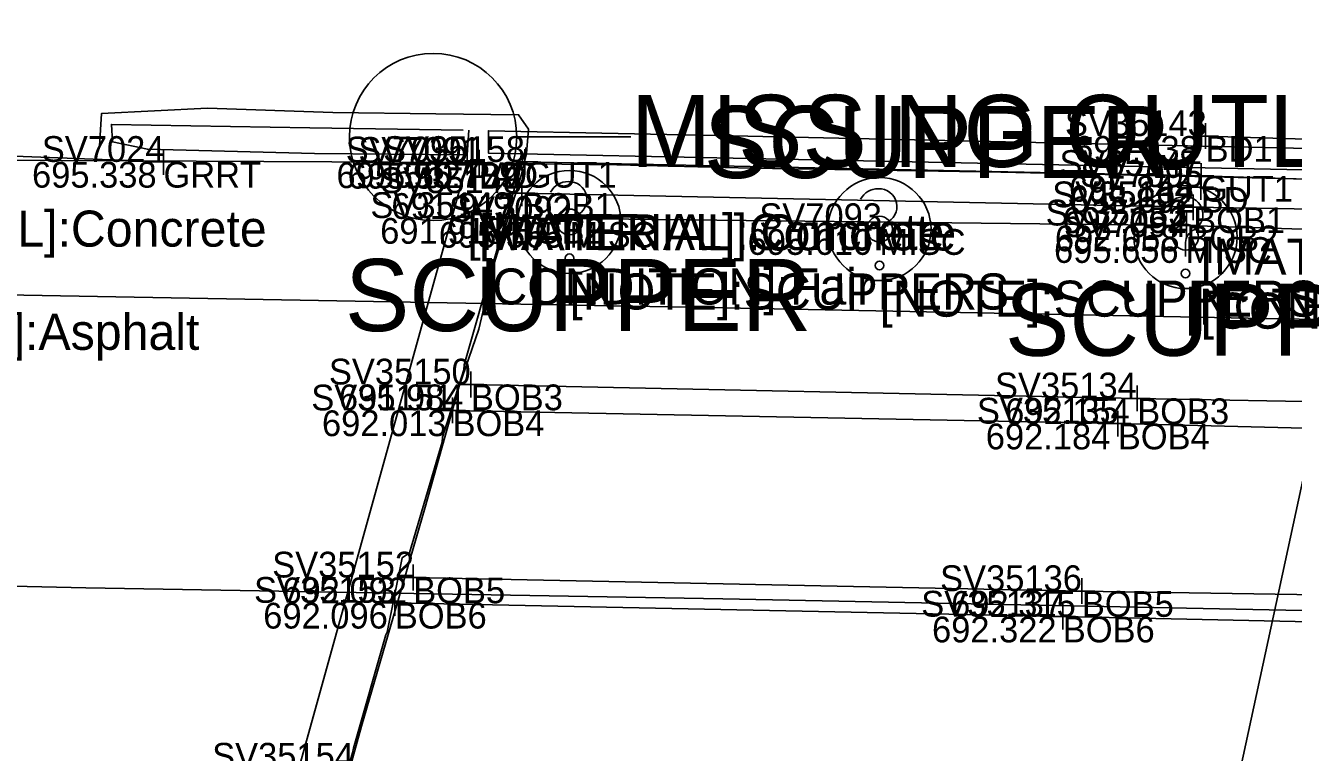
# Model space of a CAD drawing. Extents: x 1659932 to 1663108, y 619867 to 620611.
# Drawn here: x 1661219.34 to 1661268.55, y 620227.86 to 620256.09 of the extents above; entities that cross this region are included whole.
import ezdxf

# ---------------------------------------------------------------- set-up
doc = ezdxf.new("R2010")
doc.units = 0
for name, color, linetype in [('BR_X_Rail_Object', 7, 'Continuous'), ('BR_X_SV_Abut', 7, 'Continuous'), ('BR_X_SV_Bottom_of_Beam', 7, 'Continuous'), ('BR_X_SV_Bottom_of_Beam_Text', 7, 'Continuous'), ('BR_X_SV_Deck_Top', 7, 'Continuous'), ('BR_X_SV_Deck_Top_Text', 7, 'Continuous'), ('PM_X_CL_Double_Solid', 7, 'Continuous'), ('PM_X_Edge_Line', 7, 'Continuous'), ('PV_X_Curb', 7, 'Continuous'), ('RD_X_Concrete_Pad', 7, 'Continuous'), ('RD_X_GR_Rt', 7, 'Continuous'), ('RD_X_Misc_Items', 7, 'Continuous'), ('RD_X_Text', 7, 'Continuous'), ('SC_Scratch6', 7, 'Continuous'), ('SV_X_Break_Lines', 7, 'Continuous'), ('SV_X_Shot_Marker', 7, 'Continuous'), ('SV_X_Text', 7, 'Continuous'), ('SV_X_Text_Comment', 7, 'Continuous'), ('SV_X_Text_Elevation', 7, 'Continuous'), ('SV_X_Text_Name', 7, 'Continuous'), ('SV_X_Toe_of_Slope', 7, 'Continuous')]:
    doc.layers.add(name, color=color, linetype=linetype)

msp = doc.modelspace()

# ---------------------------------------------------------------- linework, layer by layer
at = {"layer": 'BR_X_Rail_Object'}
for points in [[(1661236.541, 620252.029), (1661236.482, 620251.069), (1661230.55, 620251.115), (1661224.071, 620251.281), (1661222.711, 620251.568), (1661222.675, 620252.248), (1661230.372, 620252.112), (1661236.319, 620252.019)], [(1661312.412, 620250.402), (1661292.245, 620250.78), (1661270.899, 620251.272), (1661247.366, 620251.791), (1661237.299, 620252), (1661237.309, 620251.128), (1661247.431, 620250.924), (1661270.809, 620250.444), (1661292.272, 620249.911), (1661312.353, 620249.471)]]:
    msp.add_lwpolyline(points, dxfattribs=at)
at = {"layer": 'BR_X_SV_Abut'}
msp.add_lwpolyline([(1661228.902, 620216.979), (1661231.137, 620224.905), (1661231.223, 620225.092), (1661232.028, 620227.843), (1661232.073, 620228.025), (1661233.318, 620232.429), (1661233.369, 620232.535), (1661233.962, 620235.423), (1661234.24, 620235.614), (1661235.509, 620239.905), (1661235.523, 620240.11), (1661236.345, 620242.714), (1661236.356, 620242.915), (1661238.766, 620251.347)], dxfattribs=at)
at = {"layer": 'BR_X_SV_Bottom_of_Beam'}
for points in [[(1661523.404, 620243.849), (1661497.415, 620244.383), (1661471.694, 620244.95), (1661445.773, 620245.45), (1661419.903, 620245.974), (1661394.009, 620246.51), (1661368.147, 620247.032), (1661342.287, 620247.488), (1661316.311, 620248.045), (1661290.557, 620248.602), (1661264.648, 620249.031), (1661238.6, 620249.579)], [(1661517.582, 620243.008), (1661496.897, 620243.44), (1661470.919, 620243.838), (1661445.09, 620244.441), (1661419.147, 620244.946), (1661393.26, 620245.417), (1661367.358, 620245.921), (1661341.629, 620246.518), (1661315.646, 620247.115), (1661289.746, 620247.518), (1661264.383, 620248.322), (1661238.204, 620248.614)], [(1661521.265, 620236.365), (1661495.332, 620236.959), (1661469.491, 620237.512), (1661443.572, 620237.996), (1661417.708, 620238.508), (1661391.884, 620239.08), (1661365.994, 620239.561), (1661340.119, 620240.034), (1661314.197, 620240.589), (1661288.354, 620241.145), (1661262.476, 620241.611), (1661236.623, 620242.15)], [(1661520.605, 620235.452), (1661494.63, 620235.975), (1661468.71, 620236.383), (1661442.944, 620236.996), (1661417.103, 620237.514), (1661391.103, 620237.982), (1661365.202, 620238.448), (1661339.374, 620239.07), (1661313.502, 620239.591), (1661287.59, 620239.99), (1661261.723, 620240.632), (1661235.908, 620241.144)], [(1661519.081, 620228.953), (1661493.234, 620229.438), (1661467.368, 620230.031), (1661441.422, 620230.57), (1661415.6, 620231.071), (1661389.731, 620231.651), (1661363.823, 620232.132), (1661337.817, 620232.613), (1661311.988, 620233.076), (1661286.183, 620233.721), (1661260.328, 620234.129), (1661234.382, 620234.656)], [(1661518.51, 620227.977), (1661492.527, 620228.475), (1661466.56, 620228.954), (1661440.742, 620229.56), (1661414.823, 620230.069), (1661388.938, 620230.522), (1661363.07, 620231.021), (1661337.298, 620231.612), (1661311.527, 620232.162), (1661285.446, 620232.587), (1661259.588, 620233.138), (1661233.669, 620233.674)]]:
    msp.add_lwpolyline(points, dxfattribs=at)
at = {"layer": 'BR_X_SV_Deck_Top'}
msp.add_lwpolyline([(1661524.154, 620246.519), (1661498.291, 620247.067), (1661472.426, 620247.598), (1661446.524, 620248.074), (1661420.55, 620248.604), (1661394.772, 620249.021), (1661368.927, 620249.743), (1661342.743, 620250.117), (1661316.866, 620250.706), (1661291.246, 620251.013), (1661265.132, 620251.796)], dxfattribs=at)
at = {"layer": 'PM_X_CL_Double_Solid'}
msp.add_lwpolyline([(1661546.991, 620228.003), (1661534.02, 620228.314), (1661515.703, 620228.672), (1661490.63, 620229.199), (1661465.719, 620229.574), (1661443.889, 620229.917), (1661424.27, 620230.219), (1661405.796, 620230.53), (1661384.669, 620230.881), (1661362.569, 620231.272), (1661341.508, 620231.739), (1661317.992, 620232.235), (1661293.686, 620232.891), (1661270.168, 620233.351), (1661246.396, 620233.829), (1661221.676, 620234.257), (1661205.714, 620234.618)], dxfattribs=at)
at = {"layer": 'PM_X_Edge_Line'}
msp.add_lwpolyline([(1661550.118, 620239.201), (1661538.667, 620239.519), (1661512.091, 620240.179), (1661488.878, 620240.663), (1661465.84, 620241.071), (1661441.891, 620241.445), (1661414.819, 620241.887), (1661388.375, 620242.338), (1661361.281, 620242.854), (1661333.713, 620243.371), (1661302.167, 620244.004), (1661273.353, 620244.591), (1661246.421, 620245.132), (1661216.402, 620245.664), (1661208.501, 620245.807)], dxfattribs=at)
at = {"layer": 'PV_X_Curb'}
msp.add_lwpolyline([(1661523.342, 620245.121), (1661471.566, 620246.113), (1661445.996, 620246.597), (1661316.22, 620249.01), (1661290.79, 620249.439), (1661264.952, 620250.247), (1661238.714, 620250.79)], dxfattribs=at)
at = {"layer": 'RD_X_Concrete_Pad'}
msp.add_lwpolyline([(1661227.337, 620217.837), (1661200.851, 620218.632), (1661210.18, 620250.901), (1661236.479, 620250.773)], close=True, dxfattribs=at)
at = {"layer": 'RD_X_GR_Rt'}
msp.add_lwpolyline([(1661224.694, 620250.792), (1661156.18, 620253.354), (1661087.544, 620257.195), (1661037.259, 620258.502), (1660981.367, 620259.471), (1660918.677, 620260.81), (1660856.774, 620262.085), (1660800.696, 620262.738), (1660750.309, 620264.537), (1660700.275, 620265.164), (1660644.426, 620266.521), (1660592.862, 620267.531)], dxfattribs=at)
at = {"layer": 'RD_X_Misc_Items'}
for p, q in [((1661240.447, 620247.706), (1661240.447, 620248.181)), ((1661252.475, 620247.427), (1661252.475, 620247.902)), ((1661264.352, 620247.116), (1661264.352, 620247.591))]:
    msp.add_line(p, q, dxfattribs=at)
for centre, radius in [((1661240.447, 620248.461), 2), ((1661252.475, 620248.182), 2), ((1661264.352, 620247.871), 2), ((1661240.447, 620248.461), 0.5), ((1661240.447, 620248.461), 0.5), ((1661252.475, 620248.182), 0.5), ((1661252.475, 620248.182), 0.5), ((1661264.352, 620247.871), 0.5), ((1661264.352, 620247.871), 0.5), ((1661240.447, 620247.049), 0.17), ((1661252.475, 620246.77), 0.17), ((1661264.352, 620246.459), 0.17)]:
    msp.add_circle(centre, radius, dxfattribs=at)
for centre, radius, start, end in [((1661240.383, 620249.272), 0.754, 88.324, 152.5385), ((1661240.435, 620249.339), 0.688, 291.9329, 92.4584), ((1661252.411, 620248.993), 0.754, 88.324, 152.5385), ((1661252.463, 620249.06), 0.688, 291.9329, 92.4584), ((1661264.288, 620248.682), 0.754, 88.324, 152.5385), ((1661264.34, 620248.749), 0.688, 291.9329, 92.4584), ((1661241.033, 620248.223), 0.587, 125.4618, 184.0829), ((1661253.061, 620247.944), 0.587, 125.4618, 184.0829), ((1661264.938, 620247.633), 0.587, 125.4618, 184.0829)]:
    msp.add_arc(centre, radius, start, end, dxfattribs=at)
at = {"layer": 'SC_Scratch6'}
msp.add_line((1661238.401, 620251.76), (1661242.831, 620251.76), dxfattribs=at)
msp.add_circle((1661235.157, 620251.76), 3.245, dxfattribs=at)
at = {"layer": 'SV_X_Break_Lines'}
for points in [[(1661238.852, 620252.06), (1661238.474, 620252.623), (1661235.256, 620252.659), (1661231.268, 620252.711), (1661226.404, 620252.881), (1661222.29, 620252.676), (1661222.214, 620251.401)], [(1661228.886, 620216.719), (1661229.498, 620218.302), (1661229.927, 620220.312), (1661230.763, 620223.207), (1661231.636, 620226.217), (1661232.38, 620228.883), (1661234.027, 620234.579), (1661234.843, 620237.386), (1661236.169, 620242.084), (1661236.935, 620244.302), (1661237.536, 620246.886), (1661238.567, 620250.261), (1661238.784, 620251.123), (1661238.852, 620252.06)], [(1661238.016, 620250.735), (1661242.286, 620250.672), (1661247.517, 620250.551), (1661257.182, 620250.394), (1661265.859, 620250.202), (1661279.254, 620249.879), (1661300.715, 620249.466), (1661326.88, 620248.933), (1661355.543, 620248.374), (1661388.796, 620247.704), (1661434.33, 620246.78), (1661467.071, 620246.096), (1661484, 620245.717), (1661498.395, 620245.527), (1661509.52, 620245.356), (1661518.819, 620245.069), (1661524.432, 620245.01)]]:
    msp.add_lwpolyline(points, dxfattribs=at)
at = {"layer": 'SV_X_Shot_Marker'}
for p, q in [((1661265.132, 620252.296), (1661265.132, 620251.296)), ((1661264.632, 620251.796), (1661265.632, 620251.796)), ((1661265.132, 620251.796), (1661265.132, 620251.796)), ((1661224.694, 620251.292), (1661224.694, 620250.292)), ((1661236.479, 620251.273), (1661236.479, 620250.273)), ((1661236.937, 620251.254), (1661236.937, 620250.254)), ((1661238.714, 620251.29), (1661238.714, 620250.29)), ((1661224.194, 620250.792), (1661225.194, 620250.792)), ((1661224.694, 620250.792), (1661224.694, 620250.792)), ((1661235.979, 620250.773), (1661236.979, 620250.773)), ((1661236.437, 620250.754), (1661237.437, 620250.754)), ((1661236.479, 620250.773), (1661236.479, 620250.773)), ((1661236.937, 620250.754), (1661236.937, 620250.754)), ((1661238.214, 620250.79), (1661239.214, 620250.79)), ((1661238.714, 620250.79), (1661238.714, 620250.79)), ((1661264.952, 620250.747), (1661264.952, 620249.747)), ((1661238.6, 620250.079), (1661238.6, 620249.079)), ((1661264.452, 620250.247), (1661265.452, 620250.247)), ((1661264.939, 620250.315), (1661264.939, 620249.315)), ((1661264.952, 620250.247), (1661264.952, 620250.247)), ((1661238.1, 620249.579), (1661239.1, 620249.579)), ((1661238.6, 620249.579), (1661238.6, 620249.579)), ((1661264.439, 620249.815), (1661265.439, 620249.815)), ((1661264.648, 620249.531), (1661264.648, 620248.531)), ((1661264.939, 620249.815), (1661264.939, 620249.815)), ((1661238.204, 620249.114), (1661238.204, 620248.114)), ((1661264.148, 620249.031), (1661265.148, 620249.031)), ((1661264.648, 620249.031), (1661264.648, 620249.031)), ((1661237.704, 620248.614), (1661238.704, 620248.614)), ((1661238.204, 620248.614), (1661238.204, 620248.614)), ((1661264.383, 620248.822), (1661264.383, 620247.822)), ((1661263.883, 620248.322), (1661264.883, 620248.322)), ((1661264.383, 620248.322), (1661264.383, 620248.322)), ((1661236.623, 620242.65), (1661236.623, 620241.65)), ((1661236.123, 620242.15), (1661237.123, 620242.15)), ((1661236.623, 620242.15), (1661236.623, 620242.15)), ((1661262.476, 620242.111), (1661262.476, 620241.111)), ((1661235.908, 620241.644), (1661235.908, 620240.644)), ((1661261.976, 620241.611), (1661262.976, 620241.611)), ((1661262.476, 620241.611), (1661262.476, 620241.611)), ((1661235.408, 620241.144), (1661236.408, 620241.144)), ((1661235.908, 620241.144), (1661235.908, 620241.144)), ((1661261.723, 620241.132), (1661261.723, 620240.132)), ((1661261.223, 620240.632), (1661262.223, 620240.632)), ((1661261.723, 620240.632), (1661261.723, 620240.632)), ((1661234.382, 620235.156), (1661234.382, 620234.156)), ((1661233.882, 620234.656), (1661234.882, 620234.656)), ((1661234.382, 620234.656), (1661234.382, 620234.656)), ((1661260.328, 620234.629), (1661260.328, 620233.629)), ((1661233.669, 620234.174), (1661233.669, 620233.174)), ((1661259.828, 620234.129), (1661260.828, 620234.129)), ((1661260.328, 620234.129), (1661260.328, 620234.129)), ((1661233.169, 620233.674), (1661234.169, 620233.674)), ((1661233.669, 620233.674), (1661233.669, 620233.674)), ((1661259.588, 620233.638), (1661259.588, 620232.638)), ((1661259.088, 620233.138), (1661260.088, 620233.138)), ((1661259.588, 620233.138), (1661259.588, 620233.138))]:
    msp.add_line(p, q, dxfattribs=at)
at = {"layer": 'SV_X_Toe_of_Slope'}
msp.add_lwpolyline([(1661237.229, 620169.637), (1661259.655, 620195.623), (1661277.405, 620277.795), (1661264.309, 620300.267)], dxfattribs=at)

# ---------------------------------------------------------------- texts
at = {"layer": 'BR_X_SV_Bottom_of_Beam_Text'}
for s, p in [('SV35148', (1661233.103, 620249.579)), ('SV35132', (1661259.179, 620249.031)), ('SV35149', (1661232.724, 620248.614)), ('691.913', (1661233.536, 620248.579)), ('BOB1', (1661238.6, 620248.579)), ('SV35133', (1661258.923, 620248.322)), ('692.052', (1661259.575, 620248.031)), ('BOB1', (1661264.648, 620248.031)), ('691.918', (1661233.104, 620247.614)), ('BOB2', (1661238.204, 620247.614)), ('692.058', (1661259.283, 620247.322)), ('BOB2', (1661264.383, 620247.322)), ('SV35150', (1661231.113, 620242.15)), ('SV35134', (1661256.958, 620241.611)), ('SV35151', (1661230.43, 620241.144)), ('691.984', (1661231.501, 620241.15)), ('BOB3', (1661236.623, 620241.15)), ('SV35135', (1661256.256, 620240.632)), ('692.154', (1661257.354, 620240.611)), ('BOB3', (1661262.476, 620240.611)), ('692.013', (1661230.844, 620240.144)), ('BOB4', (1661235.908, 620240.144)), ('692.184', (1661256.601, 620239.632)), ('BOB4', (1661261.723, 620239.632)), ('SV35152', (1661228.913, 620234.656)), ('SV35136', (1661254.828, 620234.129)), ('SV35153', (1661228.209, 620233.674)), ('692.092', (1661229.309, 620233.656)), ('BOB5', (1661234.382, 620233.656)), ('SV35137', (1661254.096, 620233.138)), ('692.315', (1661255.258, 620233.129)), ('BOB5', (1661260.328, 620233.129)), ('692.096', (1661228.565, 620232.674)), ('BOB6', (1661233.669, 620232.674)), ('692.322', (1661254.515, 620232.138)), ('BOB6', (1661259.588, 620232.138)), ('SV35154', (1661226.582, 620227.235))]:
    msp.add_text(s, height=1, dxfattribs=at).set_placement(p)
at = {"layer": 'BR_X_SV_Deck_Top_Text'}
for s, p in [('SV35143', (1661259.672, 620251.796)), ('SV7091', (1661232.257, 620250.754)), ('695.038', (1661260.032, 620250.796)), ('BD1', (1661265.132, 620250.796)), ('695.507', (1661231.841, 620249.754)), ('BD', (1661236.937, 620249.754)), ('SV7095', (1661260.27, 620249.815)), ('695.692', (1661259.866, 620248.815)), ('BD', (1661264.939, 620248.815))]:
    msp.add_text(s, height=1, dxfattribs=at).set_placement(p)
at = {"layer": 'RD_X_Text'}
for p in [(1661245.663, 620250.164), (1661231.736, 620244.222), (1661257.344, 620243.265)]:
    msp.add_text('SCUPPER', height=2.8, dxfattribs=at).set_placement(p)
at = {"layer": 'SC_Scratch6'}
msp.add_text('MISSING OUTLINE OF ABUTMENT', height=2.79999, dxfattribs=at).set_placement((1661242.831, 620250.594))
at = {"layer": 'SV_X_Text'}
for s, p in [('[MATERIAL]:Concrete', (1661210.18, 620247.501)), ('[MATERIAL]:Concrete', (1661236.479, 620247.373)), ('[MATERIAL]:Concrete', (1661236.937, 620247.354)), ('[MATERIAL]:Concrete', (1661264.939, 620246.415)), ('[CONDITION]:Fair', (1661236.937, 620245.254)), ('[NOTE]:SCUPPERS', (1661240.447, 620245.061)), ('[NOTE]:SCUPPERS', (1661252.475, 620244.782)), ('[NOTE]:SCUPPERS', (1661264.352, 620244.471)), ('[CONDITION]:Fair', (1661264.939, 620244.315)), ('[MATERIAL]:Asphalt', (1661208.921, 620243.495))]:
    msp.add_text(s, height=1.4, dxfattribs=at).set_placement(p)
at = {"layer": 'SV_X_Text_Comment'}
for s, p in [('GRRT', (1661224.694, 620249.792)), ('PAD', (1661236.479, 620249.773)), ('GUT1', (1661238.714, 620249.79)), ('GUT1', (1661264.952, 620249.247)), ('MISC', (1661240.447, 620247.461)), ('MISC', (1661252.475, 620247.182)), ('MISC', (1661264.352, 620246.871))]:
    msp.add_text(s, height=1, dxfattribs=at).set_placement(p)
at = {"layer": 'SV_X_Text_Elevation'}
for s, p in [('695.338', (1661219.594, 620249.792)), ('695.502', (1661231.406, 620249.773)), ('695.709', (1661233.63, 620249.79)), ('695.844', (1661259.83, 620249.247)), ('695.565', (1661235.377, 620247.461)), ('695.610', (1661247.361, 620247.182)), ('695.656', (1661259.248, 620246.871))]:
    msp.add_text(s, height=1, dxfattribs=at).set_placement(p)
at = {"layer": 'SV_X_Text_Name'}
for s, p in [('SV7024', (1661219.974, 620250.792)), ('SV7090', (1661231.767, 620250.773)), ('SV35158', (1661233.217, 620250.79)), ('SV35147', (1661259.46, 620250.247)), ('SV7092', (1661235.776, 620248.461)), ('SV7093', (1661247.813, 620248.182)), ('SV7094', (1661259.632, 620247.871))]:
    msp.add_text(s, height=1, dxfattribs=at).set_placement(p)

doc.saveas('drawing.dxf')
